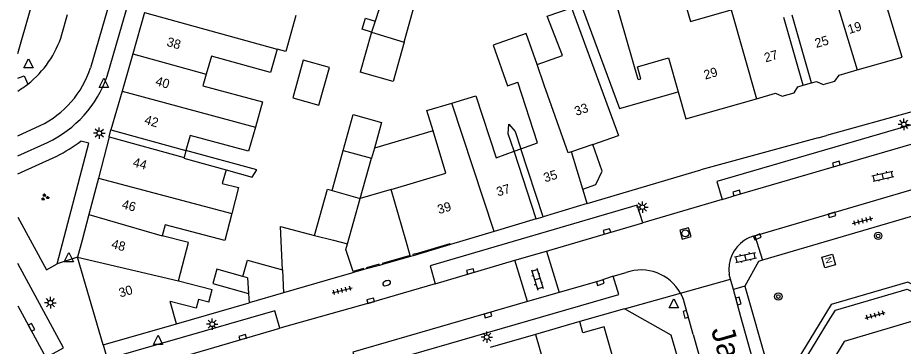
# Model space of a CAD drawing. Extents: x 132998 to 136004, y 396998 to 398512.
# Drawn here: x 133000 to 133096, y 397488.5 to 397524.1 of the extents above; entities that cross this region are included whole.
import ezdxf

# ---------------------------------------------------------------- set-up
doc = ezdxf.new("R2010")
doc.units = 0
for name, color, linetype in [('gg-afsc-erfafscheiding', 7, 'Continuous'), ('gg-afsc-hekwerk', 7, 'Continuous'), ('gg-afsc-muur', 7, 'Continuous'), ('gg-anno-huisnummerreeks BGT', 7, 'Continuous'), ('gg-anno-openbare ruimte label', 7, 'Continuous'), ('gg-bbg-bijgebouw', 7, 'Continuous'), ('gg-bbg-gedigitaliseerde bebouwing', 7, 'Continuous'), ('gg-bbg-gedigitaliseerde bebouwing onder overbouw', 7, 'Continuous'), ('gg-bbg-gedigitaliseerde bijgebouw', 7, 'Continuous'), ('gg-bbg-gedigitaliseerde overbouw', 7, 'Continuous'), ('gg-bbg-hoofdgebouw', 7, 'Continuous'), ('gg-bbg-luifel en loopbrug', 7, 'Continuous'), ('gg-bbg-pand overbouw', 7, 'Continuous'), ('gg-bbg-tussenscheiding', 7, 'Continuous'), ('gg-knt-verharding', 7, 'Continuous'), ('gg-knt-verharding nz', 7, 'Continuous'), ('gt-grn-groengrens', 7, 'Continuous'), ('gt-grn-weggrens', 7, 'Continuous'), ('gt-symb-boom', 7, 'Continuous'), ('gt-symb-brandkraan', 7, 'Continuous'), ('gt-symb-groenvak', 7, 'Continuous'), ('gt-symb-klinker verharding', 7, 'Continuous'), ('gt-symb-kolk', 7, 'Continuous'), ('gt-symb-lichtmast', 7, 'Continuous'), ('gt-symb-nortonput', 7, 'Continuous'), ('gt-symb-rioolschacht', 7, 'Continuous'), ('gt-symb-tegel verharding', 7, 'Continuous'), ('gt-symb-waterafsluiter', 7, 'Continuous')]:
    doc.layers.add(name, color=color, linetype=linetype)

# ---------------------------------------------------------------- blocks, each defined once
blk = doc.blocks.new('gt0-LMAST')
at = {"layer": 'gt-symb-lichtmast'}
for p, q in [((-0.182, 0.173), (-0.447, 0.438)), ((-0.005, 0.246), (-0.005, 0.621)), ((0.172, 0.173), (0.437, 0.438)), ((-0.255, -0.004), (-0.63, -0.004)), ((-0.182, -0.181), (-0.447, -0.446)), ((-0.005, -0.254), (-0.005, -0.629)), ((0.437, -0.446), (0.172, -0.181)), ((0.245, -0.004), (0.62, -0.004))]:
    blk.add_line(p, q, dxfattribs=at)
blk.add_circle((-0.005, -0.004), 0.25, dxfattribs=at)
blk = doc.blocks.new('gt0-TEG1')
at = {"layer": 'gt-symb-tegel verharding'}
for p, q in [((-1.125, 0), (1.125, 0)), ((-0.9, -0.25), (-0.9, 0.25)), ((-0.45, -0.25), (-0.45, 0.25)), ((0, -0.25), (0, 0.25)), ((0.45, -0.25), (0.45, 0.25)), ((0.9, -0.25), (0.9, 0.25))]:
    blk.add_line(p, q, dxfattribs=at)
blk = doc.blocks.new('gt0-KOLK')
at = {"layer": 'gt-symb-kolk'}
blk.add_lwpolyline([(0, 0), (0.375, 0), (0.375, 0.4), (-0.375, 0.4), (-0.375, 0), (0, 0)], dxfattribs=at)
blk = doc.blocks.new('gt0-KL1')
at = {"layer": 'gt-symb-klinker verharding'}
for p, q in [((-1.15, 0.3), (1.15, 0.3)), ((-1, -0.3), (-1, 0.3)), ((-0.5, 0.3), (-0.5, 0.45)), ((0, -0.3), (0, 0.3)), ((0.5, 0.3), (0.5, 0.45)), ((1, -0.3), (1, 0.3)), ((-1.15, -0.3), (1.15, -0.3)), ((-0.5, -0.45), (-0.5, -0.3)), ((0.5, -0.45), (0.5, -0.3))]:
    blk.add_line(p, q, dxfattribs=at)
blk = doc.blocks.new('gt0-WAFSL')
at = {"layer": 'gt-symb-waterafsluiter'}
for p, q in [((-0.5, -0.333), (0, 0.667)), ((0, 0.667), (0.5, -0.333)), ((0.5, -0.333), (-0.5, -0.333))]:
    blk.add_line(p, q, dxfattribs=at)
blk = doc.blocks.new('gt0-GRVAK')
at = {"layer": 'gt-symb-groenvak'}
for p, q in [((-0.11, 0.189), (-0.228, 0.24)), ((-0.182, 0.153), (0.088, 0.153)), ((-0.091, 0.211), (-0.156, 0.322)), ((-0.047, 0.214), (-0.047, 0.393)), ((-0.004, 0.211), (0.061, 0.322)), ((0.015, 0.189), (0.133, 0.24)), ((0.262, -0.052), (0.197, 0.059)), ((0.305, -0.049), (0.305, 0.13)), ((0.349, -0.052), (0.414, 0.059)), ((-0.245, -0.228), (-0.363, -0.177)), ((-0.318, -0.264), (-0.047, -0.264)), ((-0.226, -0.206), (-0.291, -0.095)), ((-0.183, -0.203), (-0.183, -0.024)), ((-0.139, -0.206), (-0.074, -0.095)), ((-0.12, -0.228), (-0.002, -0.177)), ((0.243, -0.074), (0.125, -0.023)), ((0.17, -0.11), (0.441, -0.11)), ((0.368, -0.074), (0.486, -0.023))]:
    blk.add_line(p, q, dxfattribs=at)
blk = doc.blocks.new('gt0-RS')
at = {"layer": 'gt-symb-rioolschacht'}
blk.add_lwpolyline([(-0.5, -0.5), (0.5, -0.5), (0.5, 0.5), (-0.5, 0.5)], close=True, dxfattribs=at)
blk.add_circle((0, 0), 0.375, dxfattribs=at)
blk = doc.blocks.new('gt0-BR')
at = {"layer": 'gt-symb-brandkraan'}
for centre, radius, start, end in [((-0.244, 0), 0.206, 107.56694, 252.43307), ((0.599, -2.664), 3, 106.89205, 107.56694), ((0, -0.691), 0.938, 73.10799, 106.89205), ((-0.599, -2.664), 3, 72.43309, 73.10799), ((0.244, 0), 0.206, 287.56695, 72.43309), ((0.599, 2.664), 3, 252.43307, 253.10797), ((0, 0.691), 0.938, 253.10797, 286.89206), ((-0.599, 2.664), 3, 286.89206, 287.56695)]:
    blk.add_arc(centre, radius, start, end, dxfattribs=at)
blk = doc.blocks.new('gt0-NPUT')
at = {"layer": 'gt-symb-nortonput'}
blk.add_lwpolyline([(-0.566, -0.608), (-0.566, 0.592), (0.634, 0.592), (0.634, -0.608)], close=True, dxfattribs=at)
blk.add_text('N', height=0.7, dxfattribs=at).set_placement((-0.221, -0.381))
blk = doc.blocks.new('gt0-BOOM')
at = {"layer": 'gt-symb-boom'}
for radius in [0.4, 0.2]:
    blk.add_circle((0, 0), radius, dxfattribs=at)

msp = doc.modelspace()

# ---------------------------------------------------------------- linework, layer by layer
at = {"layer": 'gg-afsc-erfafscheiding'}
for points in [[(133053.824, 397509.64), (133053.199, 397511.55), (133053.268, 397512.596), (133053.941, 397511.793), (133054.559, 397509.903)], [(133022.595, 397507.636), (133025.421, 397506.848), (133025.921, 397507.637), (133018.248, 397509.735)]]:
    msp.add_lwpolyline(points, dxfattribs=at)
at = {"layer": 'gg-afsc-hekwerk'}
for points in [[(133087.934, 397491.25), (133088.663, 397492.446), (133096.458, 397494.719), (133097.732, 397494.069)], [(133084.893, 397484.18), (133084.461, 397485.547), (133087.934, 397491.25)]]:
    msp.add_lwpolyline(points, dxfattribs=at)
at = {"layer": 'gg-afsc-muur'}
for p, q in [((133097.34, 397514.042), (133087.697, 397511.34)), ((133086.792, 397511.097), (133074.088, 397507.637)), ((133017.234, 397490.956), (133025.092, 397493.229))]:
    msp.add_line(p, q, dxfattribs=at)
at = {"layer": 'gg-bbg-bijgebouw'}
for p, q in [((133036.385, 397496.635), (133036.421, 397496.509)), ((133024.901, 397495.93), (133025.02, 397494.251)), ((133034.673, 397495.997), (133028.828, 397494.308)), ((133036.102, 397496.418), (133034.673, 397495.997)), ((133036.421, 397496.509), (133036.102, 397496.418)), ((133025.02, 397494.251), (133025.092, 397493.229)), ((133028.828, 397494.308), (133025.092, 397493.229))]:
    msp.add_line(p, q, dxfattribs=at)
msp.add_lwpolyline([(133061.27, 397505.53), (133062.68, 397506.03), (133063.39, 397507.49), (133062.38, 397510.39)], dxfattribs=at)
at = {"layer": 'gg-bbg-gedigitaliseerde bebouwing'}
for p, q in [((133067.292, 397517.414), (133064.758, 397526.217)), ((133018.038, 397508.984), (133018.018, 397508.913)), ((133018.018, 397508.913), (133022.595, 397507.636)), ((133022.595, 397507.636), (133022.185, 397506.168)), ((133017.443, 397495.595), (133021.079, 397494.659))]:
    msp.add_line(p, q, dxfattribs=at)
for points in [[(133064.758, 397526.217), (133071.673, 397528.19), (133072.951, 397523.709), (133077.355, 397524.966)], [(133056.315, 397519.059), (133059.07, 397520.026), (133057.413, 397524.297), (133060.055, 397525.189), (133065.151, 397511.34)], [(133030.153, 397524.374), (133029.066, 397520.442), (133028.127, 397520.701)], [(133056.315, 397519.059), (133055.135, 397522.419), (133051.55, 397521.16), (133053.108, 397516.725), (133054.235, 397517.121)], [(133028.127, 397520.701), (133027.404, 397518.182), (133020.997, 397519.953), (133020.439, 397518.008)], [(133020.439, 397518.008), (133020.08, 397516.743), (133026.552, 397515.007), (133025.769, 397512.276)], [(133054.559, 397509.903), (133056.376, 397510.554), (133054.235, 397517.121)], [(133045.036, 397511.875), (133044.382, 397514.063), (133047.073, 397514.868)], [(133047.073, 397514.868), (133049.672, 397515.645), (133051.875, 397508.942), (133053.824, 397509.64)], [(133025.769, 397512.276), (133025.021, 397509.673), (133018.703, 397511.367), (133018.248, 397509.735)], [(133040.484, 397505.51), (133046.41, 397507.283), (133045.036, 397511.875)], [(133022.185, 397506.168), (133023.948, 397505.709), (133023.214, 397502.887)], [(133023.214, 397502.887), (133022.458, 397499.986), (133015.991, 397501.67), (133015.681, 397500.48)], [(133017.443, 397495.595), (133018.504, 397499.761), (133015.681, 397500.48)]]:
    msp.add_lwpolyline(points, dxfattribs=at)
at = {"layer": 'gg-bbg-gedigitaliseerde bebouwing onder overbouw'}
for p, q in [((133085.176, 397516.791), (133083.085, 397524.134)), ((133086.072, 397517.046), (133083.982, 397524.386)), ((133009.918, 397511.203), (133018.038, 397508.984)), ((133010.116, 397511.956), (133018.248, 397509.735)), ((133056.215, 397502.326), (133053.824, 397509.64)), ((133056.963, 397502.55), (133054.559, 397509.903)), ((133042.071, 397500), (133040.484, 397505.51)), ((133042.541, 397498.367), (133042.071, 397500))]:
    msp.add_line(p, q, dxfattribs=at)
at = {"layer": 'gg-bbg-gedigitaliseerde bijgebouw'}
for p, q in [((133039.715, 397526.698), (133038.746, 397523.732)), ((133041.896, 397521.453), (133042.922, 397525.123)), ((133038.746, 397523.732), (133038.359, 397522.549)), ((133038.359, 397522.549), (133037.15, 397518.219)), ((133034.089, 397505.395), (133035.297, 397509.721)), ((133038.675, 397509.973), (133038.373, 397508.896)), ((133037.15, 397504.54), (133038.373, 397508.896)), ((133035.767, 397499.61), (133037.15, 397504.54)), ((133024.901, 397495.93), (133024.406, 397496.076))]:
    msp.add_line(p, q, dxfattribs=at)
for points in [[(133041.896, 397521.453), (133040.715, 397517.223), (133037.15, 397518.219)], [(133029.838, 397515.42), (133032.669, 397514.64), (133033.793, 397518.722), (133030.962, 397519.502), (133029.838, 397515.42)], [(133035.297, 397509.721), (133036.388, 397513.631), (133039.46, 397512.769), (133038.675, 397509.973)], [(133032.192, 397500.532), (133033.589, 397505.535), (133034.089, 397505.395)], [(133028.717, 397496.789), (133028.504, 397501.483), (133032.192, 397500.532)], [(133036.385, 397496.635), (133035.588, 397499.02), (133035.767, 397499.61)], [(133024.406, 397496.076), (133024.909, 397497.862), (133028.717, 397496.789)]]:
    msp.add_lwpolyline(points, dxfattribs=at)
at = {"layer": 'gg-bbg-gedigitaliseerde overbouw'}
for p, q in [((133018.248, 397509.735), (133018.038, 397508.984)), ((133053.824, 397509.64), (133054.559, 397509.903)), ((133040.484, 397505.51), (133037.15, 397504.54))]:
    msp.add_line(p, q, dxfattribs=at)
at = {"layer": 'gg-bbg-hoofdgebouw'}
for p, q in [((133013.764, 397524.671), (133012.481, 397520.2)), ((133012.481, 397520.2), (133011.319, 397516.151)), ((133089.064, 397517.898), (133091.013, 397518.453)), ((133084.611, 397516.63), (133085.176, 397516.791)), ((133086.072, 397517.046), (133086.626, 397517.204)), ((133011.319, 397516.151), (133010.116, 397511.956)), ((133080.101, 397515.345), (133082.19, 397515.94)), ((133009.918, 397511.203), (133008.743, 397506.726)), ((133062.38, 397510.39), (133065.151, 397511.34)), ((133008.743, 397506.726), (133007.709, 397502.786)), ((133061.74, 397503.98), (133061.27, 397505.53)), ((133061.74, 397503.98), (133056.963, 397502.55)), ((133056.215, 397502.326), (133051.673, 397500.967)), ((133051.673, 397500.967), (133046.94, 397499.55)), ((133009.262, 397488.666), (133006.5, 397498.17)), ((133042.577, 397498.242), (133042.541, 397498.367)), ((133042.886, 397498.33), (133042.577, 397498.242)), ((133020.729, 397493.304), (133021.079, 397494.659)), ((133017.234, 397490.956), (133016.536, 397493.386)), ((133009.262, 397488.666), (133017.234, 397490.956)), ((133060.96, 397491.19), (133056.137, 397489.792)), ((133056.137, 397489.792), (133051.236, 397488.372))]:
    msp.add_line(p, q, dxfattribs=at)
for points in [[(133000, 397520.222), (133002.771, 397529.841), (133002.932, 397530.358)], [(133091.013, 397518.453), (133095.92, 397519.85), (133094.12, 397525.815)], [(133067.292, 397517.414), (133067.58, 397517.496), (133067.209, 397518.794), (133070.575, 397519.755), (133071.621, 397516.091)], [(133086.626, 397517.204), (133087.341, 397516.875), (133088.605, 397517.234), (133089.064, 397517.898)], [(133071.621, 397516.091), (133072.455, 397513.168), (133080.101, 397515.345)], [(133082.19, 397515.94), (133082.882, 397515.615), (133084.191, 397515.99), (133084.611, 397516.63)], [(133007.709, 397502.786), (133006.977, 397500), (133006.5, 397498.17)], [(133043.124, 397498.523), (133046.908, 397499.655), (133046.94, 397499.55)], [(133043.124, 397498.523), (133042.853, 397498.446), (133042.886, 397498.33)], [(133020.729, 397493.304), (133019.592, 397493.598), (133019.35, 397492.66), (133016.536, 397493.386)], [(133065.52, 397486.061), (133064.57, 397486.58), (133064.69, 397486.83), (133063.61, 397490.63), (133061.29, 397489.97), (133060.96, 397491.19)]]:
    msp.add_lwpolyline(points, dxfattribs=at)
at = {"layer": 'gg-bbg-luifel en loopbrug'}
msp.add_line((133045.036, 397511.875), (133038.675, 397509.973), dxfattribs=at)
for points in [[(133058.202, 397533.349), (133065.25, 397514.273), (133071.621, 397516.091)], [(133038.359, 397522.549), (133037.339, 397522.865), (133037.731, 397524.063), (133038.746, 397523.732)], [(133024.406, 397496.076), (133021.592, 397496.869), (133021.16, 397495.338), (133025.02, 397494.251)]]:
    msp.add_lwpolyline(points, dxfattribs=at)
at = {"layer": 'gg-bbg-pand overbouw'}
for p, q in [((133085.176, 397516.791), (133086.072, 397517.046)), ((133009.918, 397511.203), (133010.116, 397511.956)), ((133056.215, 397502.326), (133056.963, 397502.55)), ((133042.541, 397498.367), (133039.505, 397497.502)), ((133037.488, 397496.949), (133036.385, 397496.635)), ((133037.524, 397496.823), (133037.488, 397496.949)), ((133037.833, 397496.911), (133037.524, 397496.823)), ((133039.54, 397497.377), (133039.231, 397497.288)), ((133039.505, 397497.502), (133039.54, 397497.377))]:
    msp.add_line(p, q, dxfattribs=at)
msp.add_lwpolyline([(133039.231, 397497.288), (133039.198, 397497.405), (133037.805, 397497.008), (133037.833, 397496.911)], dxfattribs=at)
at = {"layer": 'gg-bbg-tussenscheiding'}
for p, q in [((133088.27, 397527.56), (133091.013, 397518.453)), ((133013.764, 397524.671), (133028.127, 397520.701)), ((133077.355, 397524.966), (133080.101, 397515.345)), ((133038.359, 397522.549), (133041.896, 397521.453)), ((133012.481, 397520.2), (133020.439, 397518.008)), ((133011.319, 397516.151), (133025.769, 397512.276)), ((133051.673, 397500.967), (133047.073, 397514.868)), ((133062.38, 397510.39), (133060.04, 397509.587)), ((133035.297, 397509.721), (133038.373, 397508.896)), ((133061.27, 397505.53), (133060.04, 397509.587)), ((133008.743, 397506.726), (133023.214, 397502.887)), ((133034.089, 397505.395), (133037.15, 397504.54)), ((133007.709, 397502.786), (133015.681, 397500.48)), ((133032.192, 397500.532), (133034.255, 397500)), ((133034.255, 397500), (133035.767, 397499.61)), ((133006.5, 397498.17), (133017.443, 397495.595)), ((133028.717, 397496.789), (133028.828, 397494.308)), ((133056.137, 397489.792), (133059.761, 397477.277))]:
    msp.add_line(p, q, dxfattribs=at)
msp.add_lwpolyline([(133060.04, 397509.587), (133059.686, 397509.466), (133057.106, 397516.808), (133056.315, 397519.059)], dxfattribs=at)
at = {"layer": 'gg-knt-verharding'}
for p, q in [((133004.796, 397522.301), (133005.393, 397524.448)), ((133086.792, 397511.097), (133087.697, 397511.34)), ((133000, 397509.156), (133003.24, 397510.605)), ((133000, 397507.217), (133004.237, 397509.118)), ((133061.74, 397503.98), (133074.088, 397507.637)), ((133076.407, 397504.433), (133067.796, 397501.907)), ((133100.101, 397503.519), (133080.766, 397497.839)), ((133079.949, 397500.486), (133080.766, 397497.839)), ((133046.94, 397499.55), (133042.886, 397498.33)), ((133053.912, 397497.835), (133057.346, 397498.839)), ((133057.346, 397498.839), (133058.701, 397494.341)), ((133042.577, 397498.242), (133039.54, 397497.377)), ((133055.286, 397493.354), (133053.912, 397497.835)), ((133037.524, 397496.823), (133036.421, 397496.509)), ((133039.231, 397497.288), (133037.833, 397496.911)), ((133064.586, 397496.102), (133065.972, 397496.5)), ((133077.291, 397495.807), (133077.157, 397496.296)), ((133077.605, 397494.666), (133077.291, 397495.807)), ((133078.836, 397495.047), (133077.605, 397494.666)), ((133078.836, 397495.047), (133082.411, 397482.542)), ((133058.701, 397494.341), (133055.286, 397493.354)), ((133078.422, 397491.718), (133077.605, 397494.666)), ((133065.81, 397492.59), (133060.96, 397491.19)), ((133081.806, 397479.678), (133078.422, 397491.718))]:
    msp.add_line(p, q, dxfattribs=at)
for points in [[(133009.705, 397517.779), (133013.018, 397529.277), (133015.336, 397536.689), (133018.019, 397544.809), (133020.137, 397550.984), (133023.599, 397560.608)], [(133000, 397517.574), (133000.691, 397517.835), (133001.085, 397516.919)], [(133098.878, 397511), (133098.314, 397512.915), (133075.821, 397506.389), (133076.407, 397504.433)], [(133004.289, 397497.46), (133007.702, 397510.538), (133006.852, 397510.75)], [(133079.949, 397500.486), (133080.143, 397500.562), (133099.201, 397506.169), (133099.316, 397506.178)], [(133067.796, 397501.907), (133067.185, 397503.823), (133044.715, 397497.224), (133045.262, 397495.286)], [(133000, 397502.505), (133003.123, 397496.81), (133004.289, 397497.46)], [(133080.766, 397497.839), (133080.34, 397497.691), (133078.836, 397495.047)], [(133003.042, 397487.305), (133004.967, 397488.348), (133000, 397497.495)], [(133036.343, 397487.867), (133036.938, 397485.955), (133065.18, 397494.112), (133064.586, 397496.102)], [(133045.262, 397495.286), (133038.32, 397493.255), (133028.422, 397490.467)], [(133073.26, 397489.802), (133072.187, 397493.575), (133072.04, 397493.937), (133071.864, 397494.286)], [(133028.422, 397490.467), (133027.874, 397492.36), (133010.166, 397487.28), (133010.723, 397485.329)], [(133072.22, 397485.01), (133070.87, 397489.74), (133065.81, 397492.59)], [(133102.596, 397486.631), (133101.736, 397489.107), (133097.296, 397491.319), (133089.626, 397489.042), (133086.883, 397484.496), (133087.485, 397482.278)], [(133073.26, 397489.802), (133077.987, 397473.083), (133080.789, 397463.326)]]:
    msp.add_lwpolyline(points, dxfattribs=at)
for centre, radius, start, end in [((132994.274, 397525.586), 11.022, 308.16249, 342.66338), ((132997.847, 397521.965), 12.575, 295.39573, 340.55576), ((132994.367, 397525.44), 10.851, 301.27198, 308.25003), ((132996.048, 397525.151), 18.004, 297.05698, 306.87891), ((133080.838, 397496.854), 3.74, 103.75447, 122.716), ((133080.829, 397496.874), 3.717, 122.76863, 188.95094), ((133067.617, 397491.931), 4.856, 29.00645, 109.80475)]:
    msp.add_arc(centre, radius, start, end, dxfattribs=at)
at = {"layer": 'gg-knt-verharding nz'}
for p, q in [((133000, 397511.324), (133002.43, 397512.426)), ((133057.346, 397498.839), (133067.796, 397501.907)), ((133045.262, 397495.286), (133053.912, 397497.835)), ((133000, 397492.883), (133003.042, 397487.305)), ((133055.286, 397493.354), (133036.343, 397487.867)), ((133010.723, 397485.329), (133028.422, 397490.467))]:
    msp.add_line(p, q, dxfattribs=at)
for points in [[(133022.545, 397563.496), (133019.534, 397555.071), (133017.275, 397548.807), (133014.732, 397541.282), (133012.516, 397534.501), (133010.014, 397526.026), (133007.884, 397518.691)], [(133076.407, 397504.433), (133078.031, 397504.93), (133098.878, 397511)], [(133064.586, 397496.102), (133063.115, 397495.617), (133058.701, 397494.341)]]:
    msp.add_lwpolyline(points, dxfattribs=at)
msp.add_arc((132997.943, 397521.839), 10.428, 295.48757, 342.42998, dxfattribs=at)
at = {"layer": 'gt-grn-groengrens'}
msp.add_lwpolyline([(133105.159, 397489.111), (133105.02, 397489.797), (133104.367, 397489.665), (133103.733, 397491.791), (133096.529, 397495.469), (133088.207, 397493.042), (133083.698, 397485.639), (133084.026, 397484.6), (133083.601, 397484.438), (133083.849, 397483.784)], dxfattribs=at)
at = {"layer": 'gt-grn-weggrens'}
for p, q in [((133006.5, 397498.17), (133004.289, 397497.46)), ((133071.864, 397494.286), (133077.291, 397495.807)), ((133065.81, 397492.59), (133071.864, 397494.286)), ((133009.262, 397488.666), (133010.262, 397485.192))]:
    msp.add_line(p, q, dxfattribs=at)

# ---------------------------------------------------------------- block references
at = {"layer": 'gt-symb-boom'}
for p in [(133093.302, 397500.479), (133082.481, 397493.908)]:
    msp.add_blockref('gt0-BOOM', p, dxfattribs=at)
at = {"layer": 'gt-symb-brandkraan', "rotation": -162.36228444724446}
msp.add_blockref('gt0-BR', (133040.011, 397495.359), dxfattribs=at)
at = {"layer": 'gt-symb-groenvak'}
msp.add_blockref('gt0-GRVAK', (133002.946, 397504.668), dxfattribs=at)
at = {"layer": 'gt-symb-klinker verharding'}
for p, rotation in [((133093.824, 397506.95), 12.410774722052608), ((133078.931, 397498.152), 12.410774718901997), ((133056.344, 397495.798), -73.2678397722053)]:
    msp.add_blockref('gt0-KL1', p, dxfattribs=dict(at, rotation=rotation))
at = {"layer": 'gt-symb-kolk'}
for p, rotation in [((133088.814, 397508.069), 16.26020470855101), ((133078.031, 397504.93), 17.039535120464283), ((133088.237, 397502.952), -163.55871950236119), ((133063.943, 397500.769), 16.315193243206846), ((133080.143, 397500.562), -158.71983368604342), ((133049.135, 397496.437), 16.551136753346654), ((133063.115, 397495.617), -161.76430853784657), ((133038.32, 397493.255), 16.31519324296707), ((133077.958, 397493.381), -74.28274756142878), ((133050.958, 397492.103), -163.8657954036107), ((133072.631, 397492.025), 105.00891367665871), ((133001.31, 397490.473), -61.435281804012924), ((133024.436, 397489.31), 16.205185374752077)]:
    msp.add_blockref('gt0-KOLK', p, dxfattribs=dict(at, rotation=rotation))
at = {"layer": 'gt-symb-lichtmast'}
for p in [(133096.098, 397512.569), (133008.855, 397511.616), (133067.747, 397503.598), (133003.552, 397493.243), (133021.097, 397490.913), (133050.871, 397489.509)]:
    msp.add_blockref('gt0-LMAST', p, dxfattribs=at)
at = {"layer": 'gt-symb-nortonput', "rotation": 105.89818708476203}
msp.add_blockref('gt0-NPUT', (133087.937, 397497.729), dxfattribs=at)
at = {"layer": 'gt-symb-rioolschacht', "rotation": -163.73979528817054}
msp.add_blockref('gt0-RS', (133072.403, 397500.747), dxfattribs=at)
at = {"layer": 'gt-symb-tegel verharding'}
for p, rotation in [((133091.626, 397502.107), 14.591956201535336), ((133035.173, 397494.579), 14.591956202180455), ((133092.978, 397491.882), 16.079172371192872)]:
    msp.add_blockref('gt0-TEG1', p, dxfattribs=dict(at, rotation=rotation))
at = {"layer": 'gt-symb-waterafsluiter'}
for p in [(133001.18, 397519.006), (133009.337, 397516.897), (133005.552, 397498.012), (133071.15, 397492.999), (133015.213, 397489.05)]:
    msp.add_blockref('gt0-WAFSL', p, dxfattribs=at)

# ---------------------------------------------------------------- texts
at = {"layer": 'gg-anno-huisnummerreeks BGT'}
for s, rotation, p in [('19', 16.8, (133090.177, 397522.349)), ('38', 344, (133016.087, 397521.083)), ('25', 15.9, (133086.602, 397520.836)), ('27', 15.9, (133081.107, 397519.27)), ('29', 15.9, (133074.555, 397517.405)), ('40', 344, (133014.865, 397516.822)), ('33', 18.9, (133060.566, 397513.468)), ('42', 344, (133013.663, 397512.634)), ('44', 345.3, (133012.415, 397508.02)), ('35', 16.7, (133057.189, 397506.271)), ('37', 16.7, (133052.079, 397504.742)), ('46', 345.3, (133011.221, 397503.471)), ('39', 16.7, (133045.679, 397502.826)), ('48', 345.3, (133010.093, 397499.177)), ('30', 16.2, (133011.128, 397493.797))]:
    msp.add_text(s, height=1, rotation=rotation, dxfattribs=at).set_placement(p)
at = {"layer": 'gg-anno-openbare ruimte label'}
msp.add_text('Jacob van Campenstraat', height=2.5, rotation=286, dxfattribs=at).set_placement((133075.165, 397490.295))

doc.saveas('drawing.dxf')
